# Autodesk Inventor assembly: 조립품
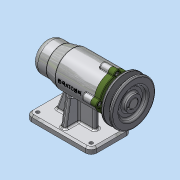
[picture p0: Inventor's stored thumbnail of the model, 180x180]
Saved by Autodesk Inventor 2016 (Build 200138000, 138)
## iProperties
Created: 2019-07
Part Number: 조립품
Material: 일반
Document SubType Name: Assembly
Designer: Administrator
Author: Administrator
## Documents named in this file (12)
- C:\Users\Administrator\Desktop\490704V1002\조립품.iam
- C:\Users\Administrator\Desktop\490704V1002\본체.ipt
- C:\Users\Administrator\Desktop\490704V1002\베어링 6004.ipt
- C:\Users\Administrator\Desktop\490704V1002\오일 실.ipt
- C:\Users\Administrator\Desktop\490704V1002\커버.ipt
- C:\Users\Administrator\Desktop\490704V1002\볼트 M4.ipt
- C:\Users\Administrator\Desktop\490704V1002\베어링 51202.ipt
- C:\Users\Administrator\Desktop\490704V1002\어댑터슬리브.ipt
- C:\Users\Administrator\Desktop\490704V1002\축.ipt
- C:\Users\Administrator\Desktop\490704V1002\V벨트풀리.ipt
- C:\Users\Administrator\Desktop\490704V1002\멈춤나사 M3.ipt
- C:\Users\Administrator\Desktop\490704V1002\키 5 x 5 x 16.ipt
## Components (1 placed, 1 different names)
1. V벨트풀리:1
